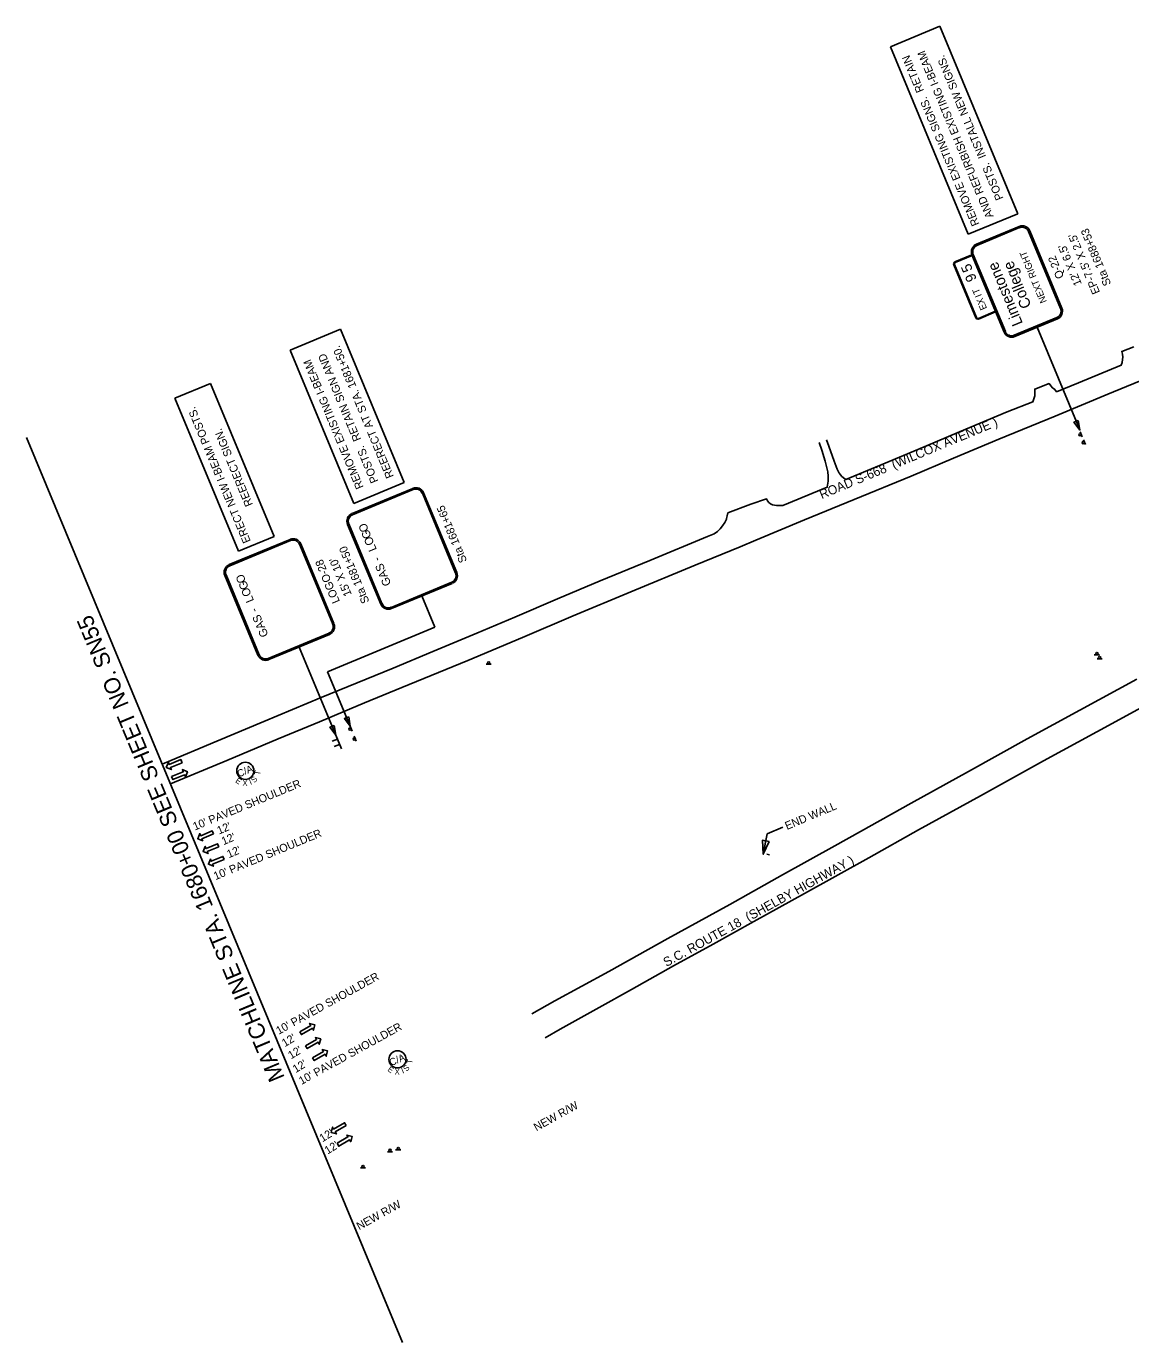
# Model space of a CAD drawing. Extents: x 1814695 to 1816409, y 1190422 to 1191819.
# Drawn here: x 1814695 to 1815661, y 1190422 to 1191573 of the extents above; entities that cross this region are included whole.
import ezdxf

# ---------------------------------------------------------------- set-up
doc = ezdxf.new("R2010")
doc.units = 0
for name, color, linetype in [('RD_EX_Road', 7, 'Continuous'), ('RD_PD_Final_LnLine', 7, 'Continuous'), ('RD_PD_Final_TX', 7, 'Continuous'), ('RD_PD_RW_TX', 7, 'Continuous'), ('RD_PD_WallFill', 7, 'Continuous'), ('RD_SHT_MatchLine', 7, 'Continuous'), ('RD_SHT_TX', 7, 'Continuous'), ('RD_Sketch8', 7, 'Continuous'), ('RD_TX_RoadID', 7, 'Continuous'), ('SN_P_Signs', 7, 'Continuous'), ('TERMINATOR', 7, 'Continuous')]:
    doc.layers.add(name, color=color, linetype=linetype)

# ---------------------------------------------------------------- blocks, each defined once
blk = doc.blocks.new('SARRW2')
at = {"layer": 'RD_PD_Final_LnLine'}
blk.add_lwpolyline([(-12, 1.2), (-12, -1.2), (-2.83, -1.2), (-2.83, -2.83), (0, 0), (-2.83, 2.83), (-2.83, 1.2)], close=True, dxfattribs=at)

msp = doc.modelspace()

# ---------------------------------------------------------------- linework, layer by layer
at = {"layer": 'RD_EX_Road'}
for points in [[(1815663.9, 1191292.9), (1815653.3, 1191288.8), (1815653.4, 1191288.7), (1815653.9, 1191286.5), (1815654.2, 1191283.9), (1815654.1, 1191281.8), (1815653.7, 1191279.3), (1815652.8, 1191276.8), (1815615.5, 1191261.4), (1815596.4, 1191253.6), (1815594.7, 1191255.5), (1815592.9, 1191256.9), (1815591.2, 1191258.7), (1815589.8, 1191260.8), (1815589.1, 1191260.5), (1815584.1, 1191258.5), (1815577.3, 1191256), (1815577.4, 1191252.2), (1815577.2, 1191249.9), (1815576.5, 1191247.3), (1815575.6, 1191244.8), (1815553.1, 1191236), (1815511.3, 1191218.4), (1815480.6, 1191205.4), (1815449.8, 1191192.5), (1815412.1, 1191176.9), (1815410, 1191178.2), (1815408.1, 1191179.8), (1815406.6, 1191181.7), (1815406.1, 1191182.4), (1815404.3, 1191185.9), (1815401.7, 1191192.8), (1815397, 1191206.1), (1815395, 1191211.5)], [(1815680.1, 1191267.5), (1815641.1, 1191251.5), (1815595.1, 1191232.3), (1815545.7, 1191212), (1815506.3, 1191195.6), (1815469.1, 1191179.9), (1815419.3, 1191159.4), (1815375.8, 1191141.5), (1815333.1, 1191123.8), (1815319.4, 1191118), (1815280.1, 1191101.9), (1815223.9, 1191078.6), (1815173.4, 1191057.5), (1815129.1, 1191038.8), (1815081.4, 1191018.6), (1815023.6, 1190995), (1814991, 1190981.4), (1814951.4, 1190965), (1814915.5, 1190950.1), (1814870.4, 1190931.2), (1814821.1, 1190910.8), (1814821, 1190910.7)], [(1814813.8, 1190928), (1814815.9, 1190928.9), (1814861.7, 1190948.1), (1814902.9, 1190965.2), (1814952.9, 1190986.1), (1815016, 1191011.9), (1815050.6, 1191026.5), (1815089.3, 1191042.6), (1815122.4, 1191056.5), (1815159.6, 1191072.5), (1815197.2, 1191088.2), (1815240.5, 1191106.1), (1815290.9, 1191126.9), (1815296.8, 1191129.2), (1815299.6, 1191131.3), (1815302, 1191133.7), (1815304.2, 1191136.4), (1815306.1, 1191139.3), (1815307.6, 1191142.3), (1815307.7, 1191142.6), (1815308.3, 1191145), (1815308.8, 1191147.7), (1815329, 1191155.2), (1815342.7, 1191159.9), (1815343.5, 1191158.3), (1815344.7, 1191156.8), (1815346.2, 1191155.6), (1815347.8, 1191154.8), (1815349.6, 1191154.3), (1815351.4, 1191154.2), (1815356.8, 1191154), (1815395.7, 1191170.1), (1815396.5, 1191175.4), (1815396.5, 1191176), (1815396.5, 1191179.7), (1815396.1, 1191183.5), (1815395.3, 1191187.1), (1815393.9, 1191192.9), (1815391.1, 1191202.4), (1815388.7, 1191209.3)], [(1815137.4, 1190709.5), (1815157.4, 1190720.8), (1815204.5, 1190746.7), (1815256.3, 1190775.3), (1815310.6, 1190805.3), (1815356.6, 1190831.1), (1815402.3, 1190856.5), (1815424.8, 1190869), (1815469.1, 1190893.7), (1815519.2, 1190921.5), (1815570.7, 1190950), (1815616.7, 1190975.1), (1815666.4, 1191002.1)], [(1815148.9, 1190688.7), (1815162.1, 1190696.1), (1815196.2, 1190715.1), (1815224.6, 1190730.9), (1815261.3, 1190751.6), (1815295.9, 1190770.6), (1815331.4, 1190790.4), (1815375.8, 1190814.8), (1815432, 1190846.1), (1815475.4, 1190870.4), (1815529.9, 1190900.3), (1815585, 1190930.9), (1815631.5, 1190956.2), (1815686.8, 1190986.3)]]:
    msp.add_lwpolyline(points, dxfattribs=at)
at = {"layer": 'RD_PD_Final_TX'}
for p, q in [((1815343.1, 1190867), (1815339.7, 1190849.1)), ((1815356.8, 1190872.8), (1815343.1, 1190867))]:
    msp.add_line(p, q, dxfattribs=at)
at = {"layer": 'RD_PD_WallFill'}
msp.add_line((1815342.8, 1190849.1), (1815345.3, 1190848.7), dxfattribs=at)
at = {"layer": 'RD_SHT_MatchLine'}
msp.add_line((1814695.1, 1191213.7), (1815024.1, 1190422), dxfattribs=at)
at = {"layer": 'RD_Sketch8'}
for centre in [(1814886.7, 1190922.1), (1815019.8, 1190669.7)]:
    msp.add_circle(centre, 7.5, dxfattribs=at)
at = {"layer": 'SN_P_Signs'}
for p, q in [((1815451, 1191555.2), (1815494.2, 1191573.2)), ((1815494.2, 1191573.2), (1815562.3, 1191409.3)), ((1815519.1, 1191391.4), (1815451, 1191555.2)), ((1815562.3, 1191409.3), (1815519.1, 1191391.4)), ((1815526.2, 1191382.7), (1815563.5, 1191398.2)), ((1815526.7, 1191381.6), (1815563.9, 1191397.1)), ((1814926, 1191289.9), (1814970, 1191308.2)), ((1814970, 1191308.2), (1815025.6, 1191174.3)), ((1815579.4, 1191310), (1815616.7, 1191220.2)), ((1814981.7, 1191156), (1814926, 1191289.9)), ((1814825.1, 1191248), (1814856.1, 1191260.9)), ((1814856.1, 1191260.9), (1814911.8, 1191127)), ((1814880.7, 1191114.1), (1814825.1, 1191248)), ((1815618.6, 1191214.2), (1815616.9, 1191218.4)), ((1815621.5, 1191207.4), (1815619.8, 1191211.6)), ((1815025.6, 1191174.3), (1814981.7, 1191156)), ((1814911.8, 1191127), (1814880.7, 1191114.1)), ((1815041.1, 1191075), (1815052.5, 1191047.7)), ((1814958.6, 1191008.7), (1815052.5, 1191047.7)), ((1814933.7, 1191030.3), (1814965.7, 1190953.4)), ((1815097.3, 1191015.4), (1815101.8, 1191015.4)), ((1815629.3, 1191023.6), (1815633.8, 1191023.6)), ((1815631.8, 1191020.1), (1815636.3, 1191020.1)), ((1814958.6, 1191008.7), (1814978.4, 1190961)), ((1814980.1, 1190956.9), (1814978.4, 1190961)), ((1814980.1, 1190956.9), (1814978.4, 1190961)), ((1814967.2, 1190949.8), (1814962.6, 1190947.9)), ((1814965.7, 1190953.4), (1814970.7, 1190941.3)), ((1814983.7, 1190948.1), (1814981.9, 1190952.3)), ((1814983.7, 1190948.1), (1814981.9, 1190952.3)), ((1814969.1, 1190945.1), (1814964.5, 1190943.2)), ((1815018.1, 1190590.7), (1815022.6, 1190590.7)), ((1815011, 1190589), (1815015.5, 1190589)), ((1814987.4, 1190575), (1814991.9, 1190575))]:
    msp.add_line(p, q, dxfattribs=at)
for points in [[(1815571.8, 1191393.8), (1815599.8, 1191326.3)], [(1815572.9, 1191394.3), (1815601, 1191326.8)], [(1815507.4, 1191367.1), (1815522.3, 1191373.3), (1815522.6, 1191372.7)], [(1815522.6, 1191372.7), (1815507.6, 1191366.5)], [(1815550.4, 1191305.8), (1815522.3, 1191373.3)], [(1815551.5, 1191306.2), (1815523.4, 1191373.7)], [(1815525.7, 1191318.2), (1815506.4, 1191364.7)], [(1815506.9, 1191364.9), (1815526.3, 1191318.4)], [(1815527.9, 1191317.7), (1815542.8, 1191324), (1815543, 1191323.4), (1815528.1, 1191317.2)], [(1815596.6, 1191318.5), (1815559.3, 1191303)], [(1815597.1, 1191317.4), (1815559.8, 1191301.9)], [(1814980, 1191147), (1815033.2, 1191169.1)], [(1814980.4, 1191145.9), (1815033.6, 1191168)], [(1815042.6, 1191165.2), (1815071.6, 1191095.4)], [(1815041.5, 1191164.8), (1815070.5, 1191095)], [(1815005.1, 1191067.8), (1814976.1, 1191137.6)], [(1815006.2, 1191068.3), (1814977.2, 1191138.1)], [(1814872.6, 1191102.4), (1814925.8, 1191124.5)], [(1814873, 1191101.3), (1814926.2, 1191123.4)], [(1814934.1, 1191120.2), (1814963.1, 1191050.3)], [(1814935.2, 1191120.6), (1814964.2, 1191050.8)], [(1814897.7, 1191023.2), (1814868.7, 1191093)], [(1814898.8, 1191023.6), (1814869.8, 1191093.4)], [(1815067.3, 1191087.1), (1815014.1, 1191065)], [(1815067.7, 1191086), (1815014.5, 1191063.9)], [(1814959.9, 1191042.5), (1814906.7, 1191020.4)], [(1814960.3, 1191041.4), (1814907.1, 1191019.3)]]:
    msp.add_lwpolyline(points, dxfattribs=at)
for points in [[(1815615.3, 1191228.5), (1815616.7, 1191220.1), (1815611.5, 1191226.9)], [(1814977.1, 1190969.4), (1814978.4, 1190961), (1814973.3, 1190967.8)], [(1814964.4, 1190961.7), (1814965.7, 1190953.4), (1814960.7, 1190960.2)]]:
    msp.add_lwpolyline(points, close=True, dxfattribs=at)
for centre in [(1815616.8, 1191215.9), (1815619.7, 1191209.1), (1815099.6, 1191016.4), (1815631.6, 1191024.6), (1815634, 1191021.1), (1814978.3, 1190958.6), (1814978.3, 1190958.6), (1814981.9, 1190949.8), (1814981.9, 1190949.8), (1815013.3, 1190590.1), (1815020.4, 1190591.7), (1814989.7, 1190576)]:
    msp.add_circle(centre, 1, dxfattribs=at)
for centre, radius, start, end in [((1815566.3, 1191391.5), 7.2, 22.5666, 112.5666), ((1815566.3, 1191391.5), 6, 22.5666, 112.5666), ((1815529, 1191376), 7.2, 112.5666, 202.5666), ((1815529, 1191376), 6, 112.5666, 202.5666), ((1815508.1, 1191365.4), 1.8, 112.5666, 202.5666), ((1815508.1, 1191365.4), 1.2, 112.5666, 202.5666), ((1815594.3, 1191324), 6, 292.5666, 22.5666), ((1815594.3, 1191324), 7.2, 292.5666, 22.5666), ((1815527.4, 1191318.9), 1.8, 202.5666, 292.5666), ((1815527.4, 1191318.9), 1.2, 202.5666, 292.5666), ((1815557, 1191308.5), 7.2, 202.5666, 292.5666), ((1815557, 1191308.5), 6, 202.5666, 292.5666), ((1815035.9, 1191162.5), 7.2, 22.5666, 112.5666), ((1815035.9, 1191162.5), 6, 22.5666, 112.5666), ((1814982.7, 1191140.4), 7.2, 112.5666, 202.5666), ((1814982.7, 1191140.4), 6, 112.5666, 202.5666), ((1814928.5, 1191117.9), 7.2, 22.5666, 112.5666), ((1814928.5, 1191117.9), 6, 22.5666, 112.5666), ((1814875.3, 1191095.7), 7.2, 112.5666, 202.5666), ((1814875.3, 1191095.7), 6, 112.5666, 202.5666), ((1815065, 1191092.7), 6, 292.5666, 22.5666), ((1815065, 1191092.7), 7.2, 292.5666, 22.5666), ((1815011.8, 1191070.6), 7.2, 202.5666, 292.5666), ((1815011.8, 1191070.6), 6, 202.5666, 292.5666), ((1814957.5, 1191048), 6, 292.5666, 22.5666), ((1814957.5, 1191048), 7.2, 292.5666, 22.5666), ((1814904.4, 1191025.9), 7.2, 202.5666, 292.5666), ((1814904.4, 1191025.9), 6, 202.5666, 292.5666)]:
    msp.add_arc(centre, radius, start, end, dxfattribs=at)
at = {"layer": 'TERMINATOR'}
msp.add_lwpolyline([(1815344.9, 1190860.3), (1815339.7, 1190849.1), (1815339, 1190861.4)], close=True, dxfattribs=at)

# ---------------------------------------------------------------- block references
at = {"layer": 'RD_PD_Final_LnLine'}
for p, xscale, yscale, rotation in [((1814817.5, 1190925), 1.2000000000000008, 1.2000000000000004, -157.44760385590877), ((1814836, 1190921.3), 1.2000000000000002, 1.2000000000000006, 22.552396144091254), ((1814845, 1190862.7), 1.2000000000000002, 1.2000000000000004, -157.44760385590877), ((1814849.7, 1190851.5), 1.2000000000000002, 1.2000000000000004, -157.44760385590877), ((1814854.3, 1190840.4), 1.2000000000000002, 1.2000000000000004, -157.44760385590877), ((1814947.5, 1190699.9), 1.1999999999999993, 1.1999999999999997, 30.219987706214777), ((1814952.6, 1190687.6), 1.1999999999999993, 1.1999999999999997, 30.219987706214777), ((1814958.6, 1190677.1), 1.1999999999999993, 1.1999999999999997, 30.219987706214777), ((1814961.7, 1190605.8), 1.1999999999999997, 1.2, -149.78001229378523), ((1814980.1, 1190602.3), 1.1999999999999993, 1.1999999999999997, 30.219987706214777)]:
    msp.add_blockref('SARRW2', p, dxfattribs=dict(at, xscale=xscale, yscale=yscale, rotation=rotation))

# ---------------------------------------------------------------- texts
at = {"layer": 'RD_PD_Final_TX'}
for s, rotation, p in [("10' PAVED SHOULDER", 22.4268, (1814842.5, 1190869.8)), ('END WALL', 22.8166, (1815360.5, 1190870.3)), ("12'", 22.759, (1814863.6, 1190866.3)), ("10' PAVED SHOULDER", 22.4268, (1814860.6, 1190826.4)), ("12'", 22.759, (1814867.5, 1190857)), ("12'", 22.759, (1814872.2, 1190845.6)), ("10' PAVED SHOULDER", 28.9296, (1814915.9, 1190691.2)), ("10' PAVED SHOULDER", 28.9296, (1814935.8, 1190647.3)), ("12'", 31.3888, (1814921.2, 1190680.3)), ("12'", 31.3888, (1814926.6, 1190669.6)), ("12'", 31.3888, (1814930.7, 1190657.6)), ("12'", 31.3888, (1814954.1, 1190597.1)), ("12'", 31.3888, (1814958.6, 1190586.4))]:
    msp.add_text(s, height=7, rotation=rotation, dxfattribs=at).set_placement(p)
at = {"layer": 'RD_PD_RW_TX'}
for p in [(1815141.3, 1190606.7), (1814986.3, 1190520.2)]:
    msp.add_text('NEW R/W', height=7, rotation=29.0102, dxfattribs=at).set_placement(p)
at = {"layer": 'RD_SHT_TX'}
msp.add_text('MATCHLINE STA. 1680+00 SEE SHEET NO. SN55', height=14.173, rotation=112.6789, dxfattribs=at).set_placement((1814921.3, 1190653.8))
at = {"layer": 'RD_Sketch8'}
for s, height, rotation, p in [('C/A', 6.25, 22.5666, (1814881.1, 1190916.3)), ('E', 5, 325.7778, (1814877.5, 1190912.4)), ('X', 5, 358.2072, (1814884.1, 1190909)), ('I', 5, 22.3672, (1814891.2, 1190909.7)), ('S', 5, 44.359, (1814894.5, 1190911.2)), ('T', 5, 80.7517, (1814899.4, 1190918)), ('C/A', 6.25, 22.5666, (1815014.2, 1190663.8)), ('T', 5, 80.7517, (1815032.5, 1190665.5)), ('E', 5, 325.7778, (1815010.6, 1190659.9)), ('X', 5, 358.2072, (1815017.2, 1190656.5)), ('I', 5, 22.3672, (1815024.3, 1190657.2)), ('S', 5, 44.359, (1815027.6, 1190658.7))]:
    msp.add_text(s, height=height, rotation=rotation, dxfattribs=at).set_placement(p)
at = {"layer": 'RD_TX_RoadID'}
for s, rotation, p in [('ROAD S-668  (WILCOX AVENUE )', 22.6357, (1815390.9, 1191159.6)), ('S.C. ROUTE 18  (SHELBY HIGHWAY )', 28.8878, (1815255, 1190750.4))]:
    msp.add_text(s, height=8, rotation=rotation, dxfattribs=at).set_placement(p)
at = {"layer": 'SN_P_Signs'}
for s, height, rotation, p in [('REMOVE EXISTING SIGNS.  RETAIN', 7, 112.5667, (1815529, 1191400.2)), ('AND REFURBISH EXISTING I-BEAM', 7, 112.5667, (1815541.3, 1191407.1)), ('POSTS.  INSTALL NEW SIGNS.', 7, 112.5667, (1815550, 1191422.8)), ('Sta 1688+53', 7, 112.5667, (1815644.2, 1191347.9)), ("EP-7.5' X 2.5'", 7, 112.5667, (1815634.4, 1191340.6)), ('NEXT RIGHT', 6, 112.5666, (1815587.9, 1191332.5)), ('Q-22', 7, 112.5667, (1815603, 1191354.1)), ("12' X 6.5'", 7, 112.5667, (1815618.5, 1191347.9)), ('5', 9, 112.5666, (1815523.2, 1191360.3)), ('Limestone', 9.6, 112.5666, (1815567, 1191313.4)), ('College', 9.6, 112.5666, (1815574.5, 1191328.7)), ('9', 9, 112.5666, (1815526.7, 1191351.9)), ('T', 6, 112.5666, (1815529.8, 1191340.3)), ('I', 6, 112.5666, (1815531, 1191337.6)), ('X', 6, 112.5666, (1815533.6, 1191331.3)), ('E', 6, 112.5666, (1815535.6, 1191326.5)), ('REERECT AT STA. 1681+50.', 7, 112.5667, (1815016.7, 1191179.6)), ('REMOVE EXISTING I-BEAM', 7, 112.5667, (1814990.3, 1191170.2)), ('POSTS.  RETAIN SIGN AND', 7, 112.5667, (1815003.2, 1191175.4)), ('ERECT NEW I-BEAM POSTS.', 7, 112.5667, (1814891.5, 1191122.9)), ('REERECT SIGN.', 7, 112.5667, (1814893.4, 1191154.9)), ('Sta 1681+65', 7, 112.5667, (1815080.7, 1191105.7)), ('O', 7.2, 112.5666, (1814994.8, 1191132.5)), ('O', 7.2, 112.5666, (1814994.8, 1191132.5)), ('G', 7.2, 112.5666, (1814997.2, 1191126.8)), ('G', 7.2, 112.5666, (1814997.2, 1191126.8)), ('O', 7.2, 112.5666, (1814999.6, 1191120.9)), ('O', 7.2, 112.5666, (1814999.6, 1191120.9)), ('L', 7.2, 112.5666, (1815001.8, 1191115.6)), ('L', 7.2, 112.5666, (1815001.8, 1191115.6)), ('Sta 1681+50', 7, 112.5667, (1814995.3, 1191070.1)), ('-', 7.2, 112.5666, (1815005.4, 1191106.9)), ('-', 7.2, 112.5666, (1815005.4, 1191106.9)), ('LOGO-28', 7, 112.5667, (1814969.5, 1191070.2)), ("15' X 10'", 7, 112.5667, (1814979.9, 1191076.3)), ('GAS', 7.2, 112.5666, (1815014.4, 1191085.4)), ('O', 7.2, 112.5666, (1814887.4, 1191087.9)), ('O', 7.2, 112.5666, (1814887.4, 1191087.9)), ('G', 7.2, 112.5666, (1814889.8, 1191082.2)), ('G', 7.2, 112.5666, (1814889.8, 1191082.2)), ('O', 7.2, 112.5666, (1814892.2, 1191076.2)), ('O', 7.2, 112.5666, (1814892.2, 1191076.2)), ('L', 7.2, 112.5666, (1814894.4, 1191070.9)), ('L', 7.2, 112.5666, (1814894.4, 1191070.9)), ('-', 7.2, 112.5666, (1814898, 1191062.3)), ('-', 7.2, 112.5666, (1814898, 1191062.3)), ('GAS', 7.2, 112.5666, (1814907, 1191040.7))]:
    msp.add_text(s, height=height, rotation=rotation, dxfattribs=at).set_placement(p)

doc.saveas('drawing.dxf')
